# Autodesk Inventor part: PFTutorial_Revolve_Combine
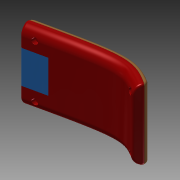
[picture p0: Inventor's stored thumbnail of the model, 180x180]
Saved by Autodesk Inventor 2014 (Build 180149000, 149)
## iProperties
Created: 2008-04
Part Number: PFTutorial_Revolve_Combine
Document SubType Name: Modeling
Designer: gpbassi
Density: 1 g/cm^3
Material: Generic
Appearance: Default
Author: gpbassi
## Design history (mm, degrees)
sketch "SpineSketch"
  geometry: 4 further points
  constraints: 4 other
node "GrillWorkPlane"
node "RestWorkPlane"
node "BossWorkPlane1"
sketch "BossSketch1"
  geometry: 2 further points
node "BossWorkPlane2"
sketch "BossSketch2"
  geometry: 2 further points
sketch "Revolve_NewBody"
  geometry: L1 (-11.76, 31.812)-(-11.76, 29.5); L2 (-11.76, 29.5)-(-7.25, 29.5); L3 (-7.25, 29.5)-(-7.25, 28.5); L4 (-7.25, 28.5)-(-11.76, 28.5); L5 (-11.76, 28.5)-(-11.76, 25.75); L6 (-11.76, 25.75)-(-8, 25.75); L7 (-8, 25.75)-(-8, 17.5); L8 (-8, 17.5)-(0, 17.5); L9 (0, 17.5)-(0, 0); L10 (0, 37.5)-(0, 17.5); A1 r 15 centre (0, 22.5) between (0, 37.5) and (-11.76, 31.812); 2 further points
  constraints: 20 end point, 5 parallel, 3 collinear, 2 coincident, 2 perpendicular, 2 point on circle, 1 centre point, 1 horizontal, 1 point on line
  dimensions: "d121" = 15 radius of A1; "d122" = 20 distance of L10.start L8.end; "d123" = 8 distance of L7.end L8.end; "d124" = 17.5 distance from line of L8 point (0, 0); "d125" = 7.25 distance between parallel lines of L3 L10; "d126" = 11.75984 distance between parallel lines of L1 L10; "d127" = 8.25 distance between parallel lines of L6 L8; "d128" = 12 distance between parallel lines of L2 L8; "d129" = 11 distance between parallel lines of L4 L8
node "SectionWorkPlane"
sketch "SectionSketch"
  geometry: L1 (17, 0)-(-19, 0) reference; L2 (0, -51)-(0, 53) reference; L3 (-14, -39.559)-(-14, 39.559); L4 (5, 52.635)-(5, -52.635); A1 r 14 centre (0, -39.559) between (-14, -39.559) and (5, -52.635); A2 r 14 centre (0, 39.559) between (5, 52.635) and (-14, 39.559); 2 further points
  constraints: 8 end point, 5 point on circle, 3 point on line, 3 symmetric about line, 2 centre point, 1 horizontal, 1 parallel, 1 perpendicular, 1 tangent, 1 vertical, 1 other
  dimensions: "d96" = 19 distance between parallel lines of L3 L4; "d97" = 5 distance between parallel lines of L4 L2
sweep "Sweep1" sketch "SectionSketch" dims "d62" = 0
extrude_surface "PartingSurface" dims "d63" = 134, "d64" = 0
sketch "GrillSketch"
  geometry: L1 (-59.25, -36.361)-(-59.25, 36.361); L2 (-100.75, 36.361)-(-100.75, -36.361); L3 (-62, -50)-(-62, 50); L4 (-66, -50)-(-66, 50); L5 (-70, -50)-(-70, 50); L6 (-74, -50)-(-74, 50); L7 (-78, -50)-(-78, 50); L8 (-82, -50)-(-82, 50); L9 (-86, -50)-(-86, 50); L10 (-90, -50)-(-90, 50); L11 (-94, -50)-(-94, 50); L12 (-98, -50)-(-98, 50); L13 (-102, 0)-(-57, 0) reference; L14 (-80, -47)-(-80, 47) reference; A1 r 32 centre (-80, -12) between (-100.75, -36.361) and (-59.25, -36.361); A2 r 32 centre (-80, 12) between (-59.25, 36.361) and (-100.75, 36.361); A3 r 32 centre (-80, 12) between (-106.819, -5.457) and (-52.691, -4.68); A4 r 32 centre (-80, -12) between (-52.691, 4.68) and (-106.819, 5.457)
  constraints: 28 end point, 8 point on circle, 4 centre point, 3 parallel, 3 symmetric about line, 1 coincident, 1 horizontal, 1 perpendicular, 1 vertical, 4 other
  dimensions: "d82" = 32 radius of A1; "d83" = 20.75 distance between parallel lines of L2 L14; "d84" = 32 radius of A2; "d85" = 32 radius of A3
sketch "RestSketch"
  geometry: L1 (34, 0)-(-25, 0); L2 (34, 0)-(-25, 0); L3 (-7.849, 32.548)-(-13.735, 2.71); L4 (-8, -31)-(-8, -11.489); L5 (7.849, -32.548)-(13.735, -2.71); L6 (8, 31)-(8, 11.489); A1 r 8 centre (0, -31) between (-8, -31) and (7.849, -32.548); A2 r 8 centre (0, 31) between (8, 31) and (-7.849, 32.548); A3 r 14 centre (0, 0) between (13.735, -2.71) and (8, 11.489); A4 r 14 centre (0, 0) between (-13.735, 2.71) and (-8, -11.489)
  constraints: 12 end point, 8 point on circle, 6 tangent, 4 centre point, 2 horizontal, 1 parallel, 1 perpendicular, 1 point on line
feature "BatterySplitSurface" dims "d120" = 0.254 (derived)
workpoint "Work Point3"
workpoint "Work Point4"
shell "Shell1" dims "d133" = 1.5
split "Split2"
  body "Solid1"
feature "Grill1" dims "d136" = 2, "d137" = 0, "d138" = 0, "d139" = 1.3, "d140" = 0.2, "d141" = 2.5, "d142" = 0.5, "d143" = 0, "d144" = 5, "d145" = 0, "d146" = 0, "d147" = 0, "d148" = 119.99372
feature "Rule Fillet1" dims "d149" = 0.5, "d150" = 1 deg
feature "Rest1" dims "d151" = 5, "d152" = 0, "d153" = 0, "d154" = 0, "d155" = 0, "d156" = 0, "d157" = 1.5
feature "Lip1" dims "d158" = 1, "d159" = 0.75, "d160" = 0, "d161" = 0, "d162" = 0, "d163" = 0.5
feature "Lip2" dims "d164" = 1, "d165" = 0.75, "d166" = 0, "d167" = 0, "d168" = 0, "d169" = 0
split "Split3"
  body "Solid3"
workplane "Work Plane11"
workplane "Work Plane12"
feature "Lip3" dims "d172" = 0.8, "d173" = 0.75, "d174" = 0, "d175" = 0, "d176" = 0, "d177" = 0
feature "Lip4" dims "d178" = 0.8, "d179" = 0.75, "d180" = 0, "d181" = 0, "d182" = 0, "d183" = 0
sketch "Sketch13"
  geometry: L1 (0, 0)-(0, 48) reference; L2 (-1.5, 48)-(0, 48) reference; L3 (-1.5, 0)-(0, 0) reference; 3 further points
  constraints: 2 point on line
  dimensions: "d184" = 7.5 distance from line of point (0, 7.5) L3; "d185" = 7.5 distance from line of point (0, 40.5) L2 (derived)
feature "Snap Fit1" sketch "Sketch13" dims "d186" = 4, "d187" = 0.5, "d188" = 0.3, "d189" = 5, "d190" = 2, "d191" = 0.5, "d192" = 0.5, "d193" = 0.5
feature "Rule Fillet2" dims "d194" = 0.2
feature "Boss1" dims "d195" = 0.3, "d196" = 8, "d197" = 1.5, "d198" = 0.5, "d199" = 7, "d200" = 1.5, "d201" = 3, "d202" = 2.5 deg, "d203" = 2.5 deg, "d204" = 2.5 deg, "d205" = 2.5 deg, "d206" = 90 deg, "d209" = 2, "d210" = 2, "d211" = 10, "d212" = 0, "d213" = 10 deg, "d214" = 2.5 deg, "d215" = 0, "d216" = 0, "d217" = 0, "d262" = 0, "d263" = 360 deg
feature "Boss2" dims "d218" = 0.3, "d219" = 8, "d220" = 3, "d221" = 9.5, "d222" = 2 deg, "d223" = 1 deg, "d226" = 1.5, "d227" = 2, "d228" = 6, "d229" = 1, "d230" = 10 deg, "d231" = 1.5 deg, "d232" = 0.2, "d233" = 0.2, "d234" = 0, "d264" = 0, "d265" = 360 deg
hole "Hole1" diameter "d237" = 10; stored, may be unused: countersink angle "d241" = 90 deg, drill point angle "d243" = 118 deg; dims "d235" = 10, "d236" = 10, "d238" = 6, "d239" = 4, "d240" = 2, "d242" = 2
hole "Hole2" diameter "d246" = 10; stored, may be unused: countersink angle "d250" = 90 deg, drill point angle "d252" = 118 deg; dims "d244" = 10, "d245" = 10, "d247" = 6, "d248" = 4, "d249" = 2, "d251" = 2
hole "Hole3" diameter "d255" = 20; stored, may be unused: countersink angle "d259" = 90 deg, drill point angle "d261" = 118 deg; dims "d253" = 10, "d254" = 10, "d256" = 6, "d257" = 4, "d258" = 2, "d260" = 2
fillet "Fillet1" dims "d98" = 8
fillet "Fillet2" dims "d99" = 3
workpoint "Work Point1"
workpoint "Work Point2"
body "Srf1"
sketch "BatterySketch"
  geometry: L1 (-10.134, -25)-(-18, -25); L2 (-18, -25)-(-18, 25); L3 (-18, 25)-(-10.134, 25); L4 (-9.134, 24)-(-9.134, -24); L5 (2, 0)-(-25, 0) reference; A1 r 1 centre (-10.134, -24) between (-10.134, -25) and (-9.134, -24); A2 r 1 centre (-10.134, 24) between (-9.134, 24) and (-10.134, 25)
  constraints: 10 end point, 4 point on circle, 4 tangent, 2 centre point, 2 horizontal, 2 parallel, 2 perpendicular, 1 equal radius, 1 other
  dimensions: "d104" = 1 radius of A1
body "Srf3"
body "Srf4"
body "Srf2"
extrude_surface "ExtrusionSrf3" dims "d105" = 36, "d106" = 0
patch "Boundary Patch1" dims "d107" = 0, "d108" = 0, "d109" = 0
body "Solid2"
body "Solid4"
body "Solid5"
other parameters: "d102" = 24, "d110" = 4.5, "d115" = 11.75, "d134" = 2.5, "d135" = 5, "d170" = -15, "d171" = -15
